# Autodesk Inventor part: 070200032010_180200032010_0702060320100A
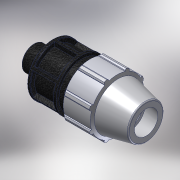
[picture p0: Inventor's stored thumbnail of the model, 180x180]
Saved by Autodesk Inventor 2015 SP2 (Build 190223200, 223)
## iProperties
Created: 2017-02
Part Number: 070200032010_180200032010_0702060320100A
Material: PVC-Piping
Description: PLASSON MALE ADAPTOR 32-1"
Document SubType Name: Modeling
Designer: KIM
Mass: 92.6774 g
Surface Area: 199.44 cm^2
Volume: 66.1981 cm^3
Density: 1.4 g/cm^3
Appearance: PTFE
Author: KIM
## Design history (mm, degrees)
derived "07020.ipt"
feature "Solid1::07020.ipt"
tag "TaggingFeature1"
body "Solid1"
other parameters: "d2" = 32, "d4" = 15.28571, "d5" = 26.75, "d7" = 64, "d8" = 48, "d9" = 15.28571, "d11" = 3.05714, "d12" = 51.2, "d13" = 120 deg, "d14" = 48, "d15" = 10 deg, "d16" = 57.6, "d18" = 1.6, "d19" = 35 deg, "d20" = 17.5 deg, "d21" = 59.52, "d23" = 0, "d25" = 360 deg, "d27" = 1.28, "d34" = 3.2, "d36" = 0, "d42" = 26.75, "d43" = 1.92, "d46" = 0.96, "d49" = 83, "d51" = 107, "d53" = 0.64, "d55" = 360 deg, "d57" = 33.249, "d58" = 23.2743, "d59" = 21.4, "d_" = 32, "E_" = 64, "H_" = 107, "l_" = 83, "R_" = 33.249
